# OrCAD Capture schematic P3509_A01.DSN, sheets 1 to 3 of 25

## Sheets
1 0024_MECHANICAL: size Custom
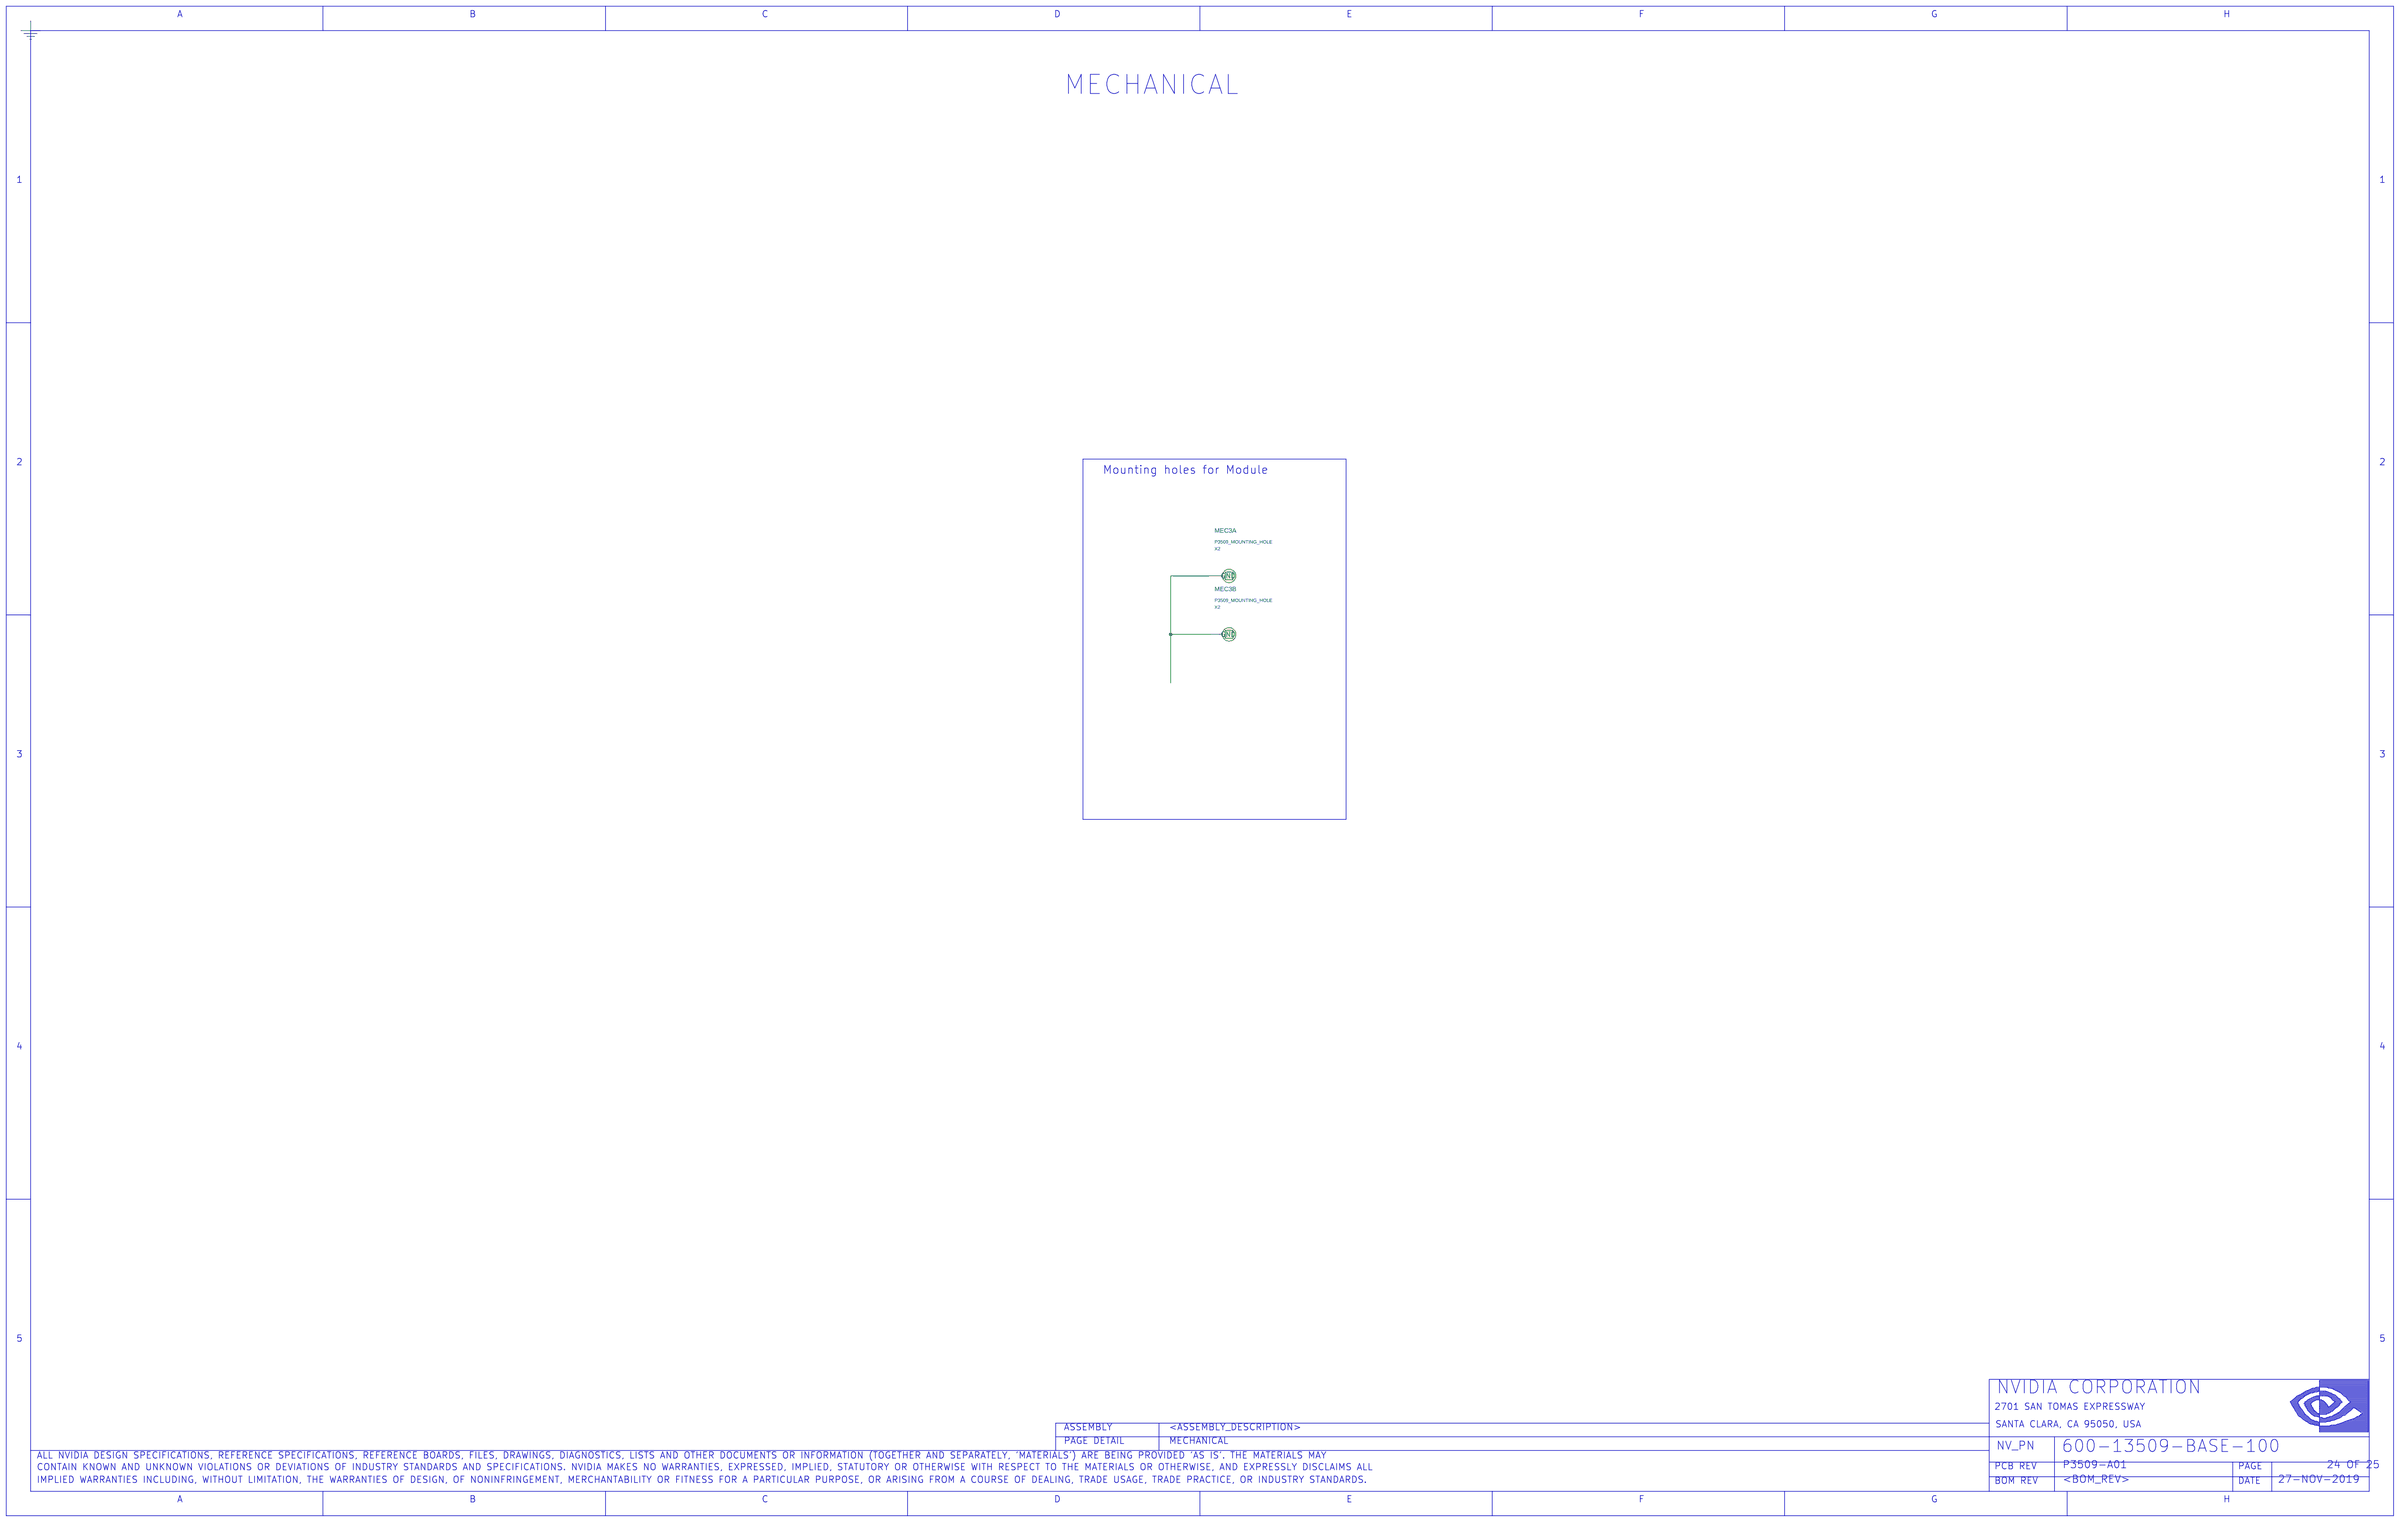
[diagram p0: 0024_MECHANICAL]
2 0023_FAN, DEBUG and EEPROM: size Custom
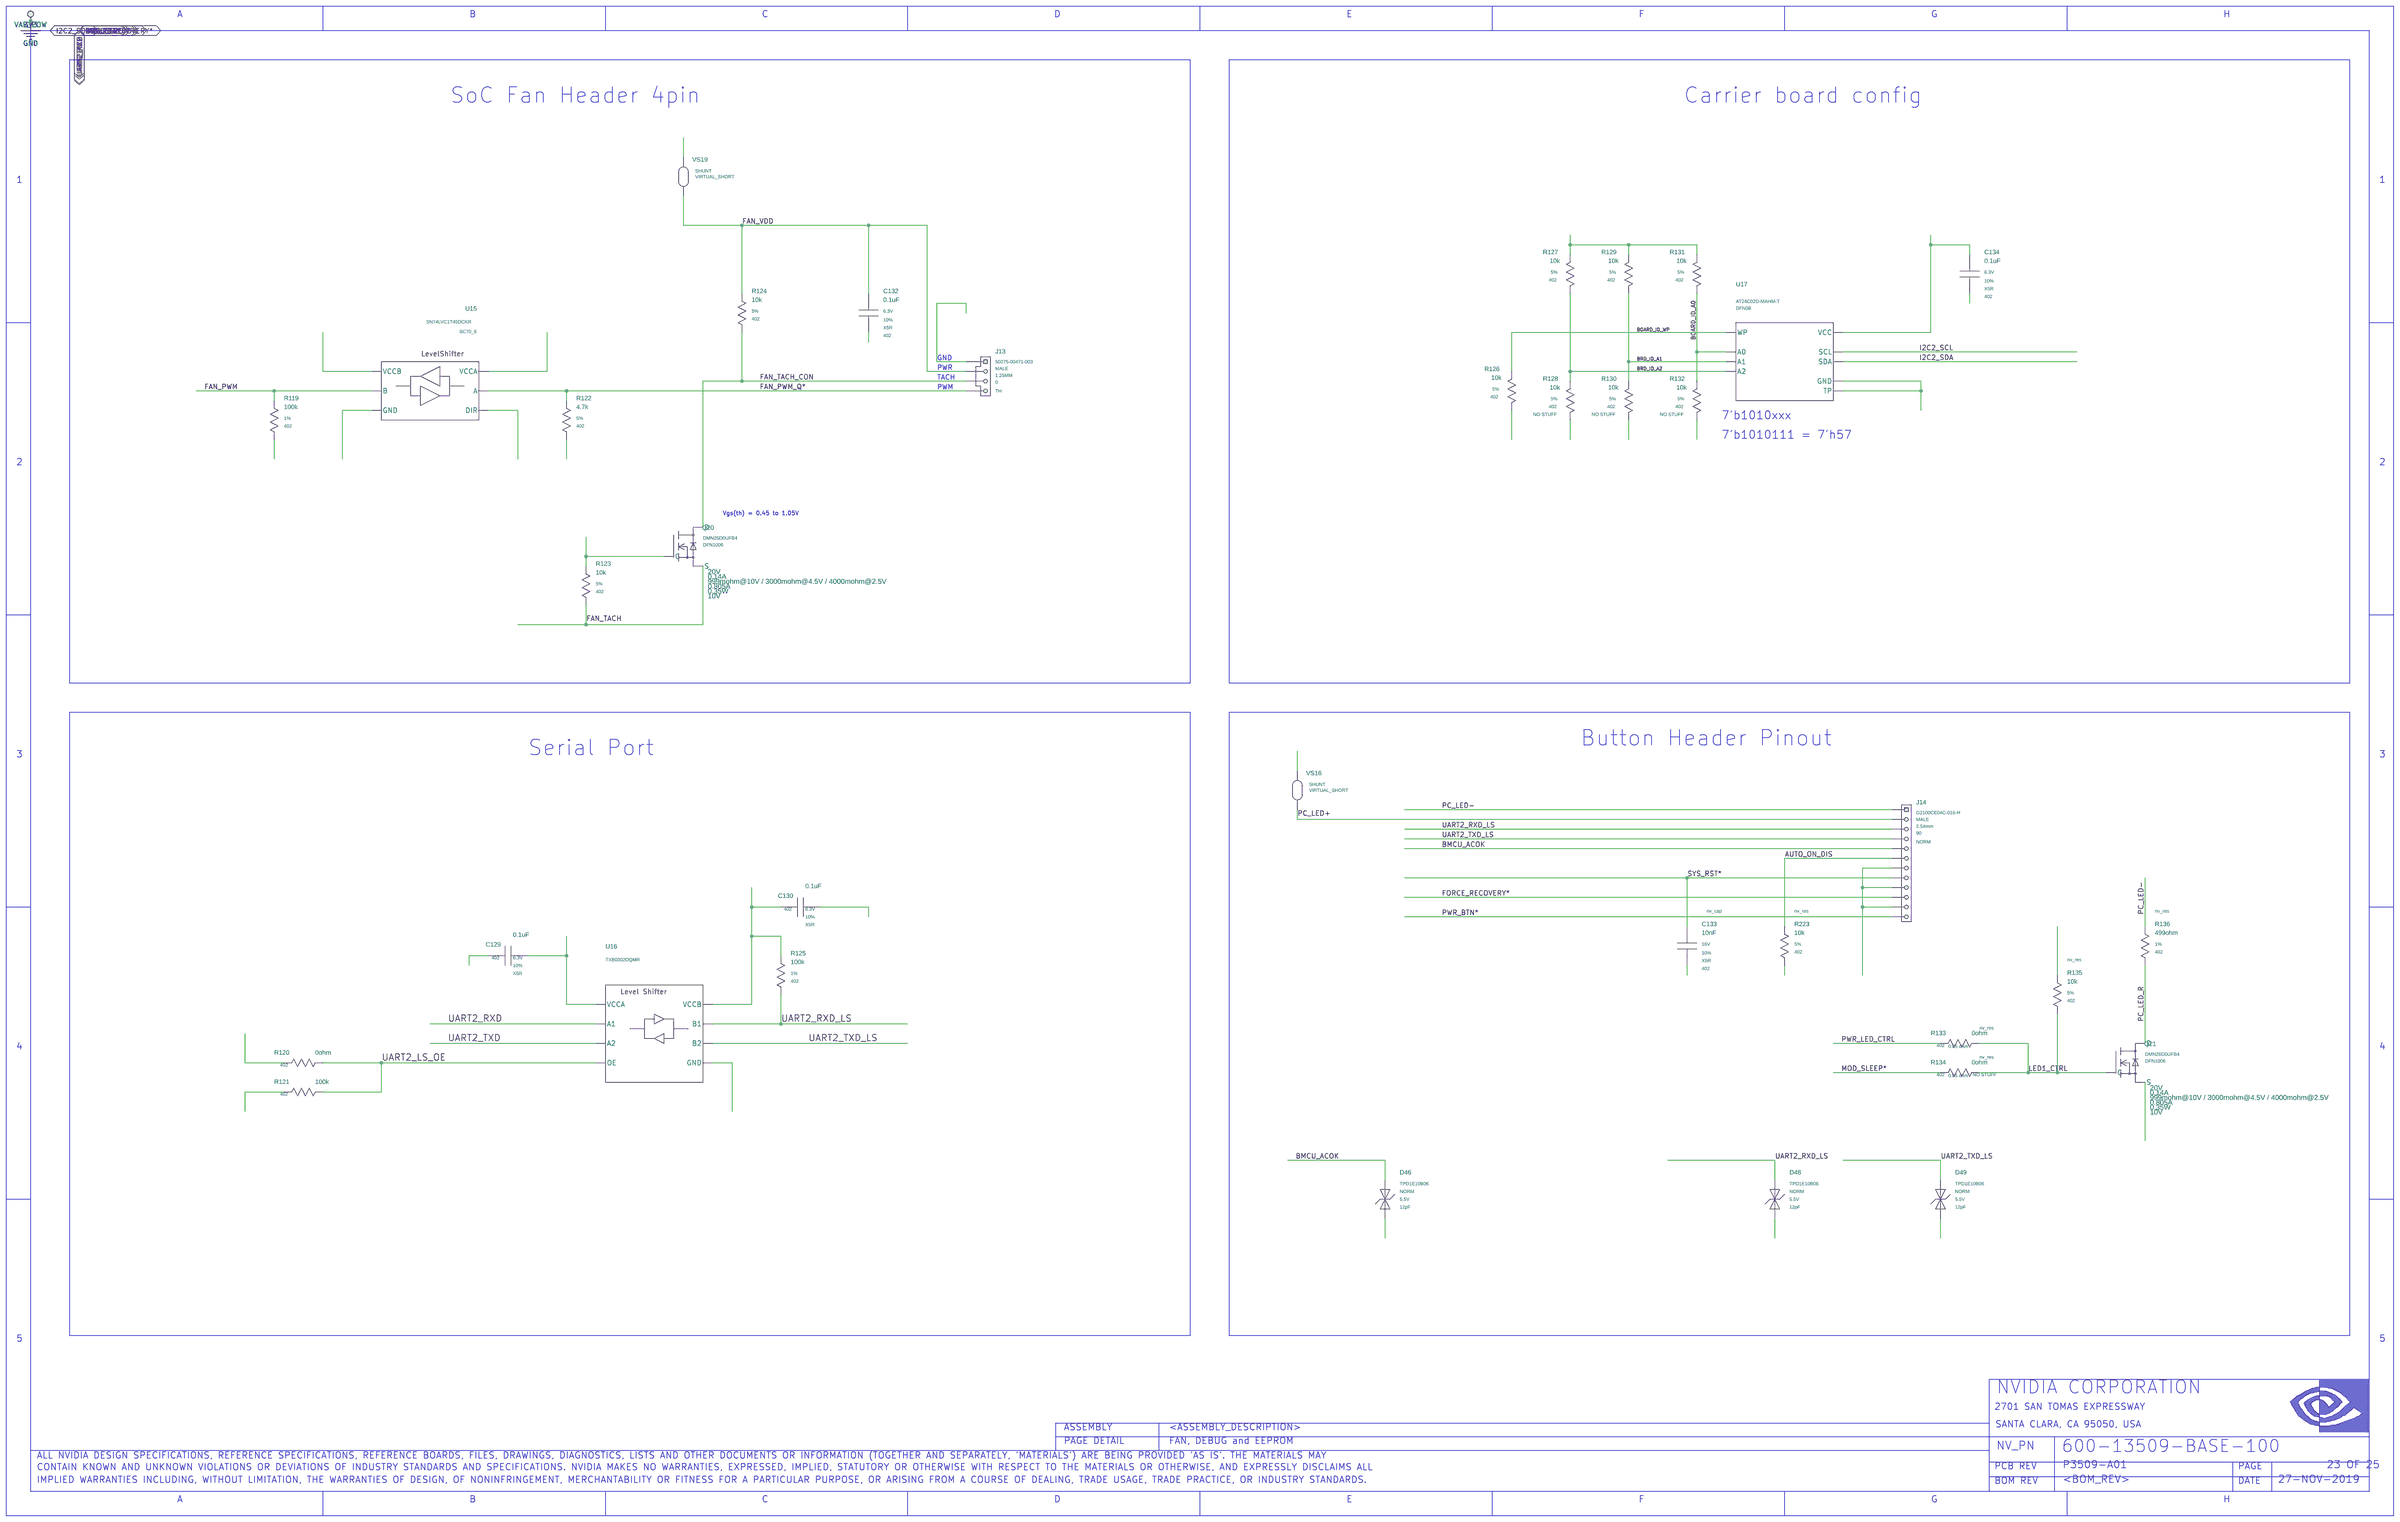
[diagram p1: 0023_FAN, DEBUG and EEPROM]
3 0022_40PIN GPIO Expansion HDR: size Custom
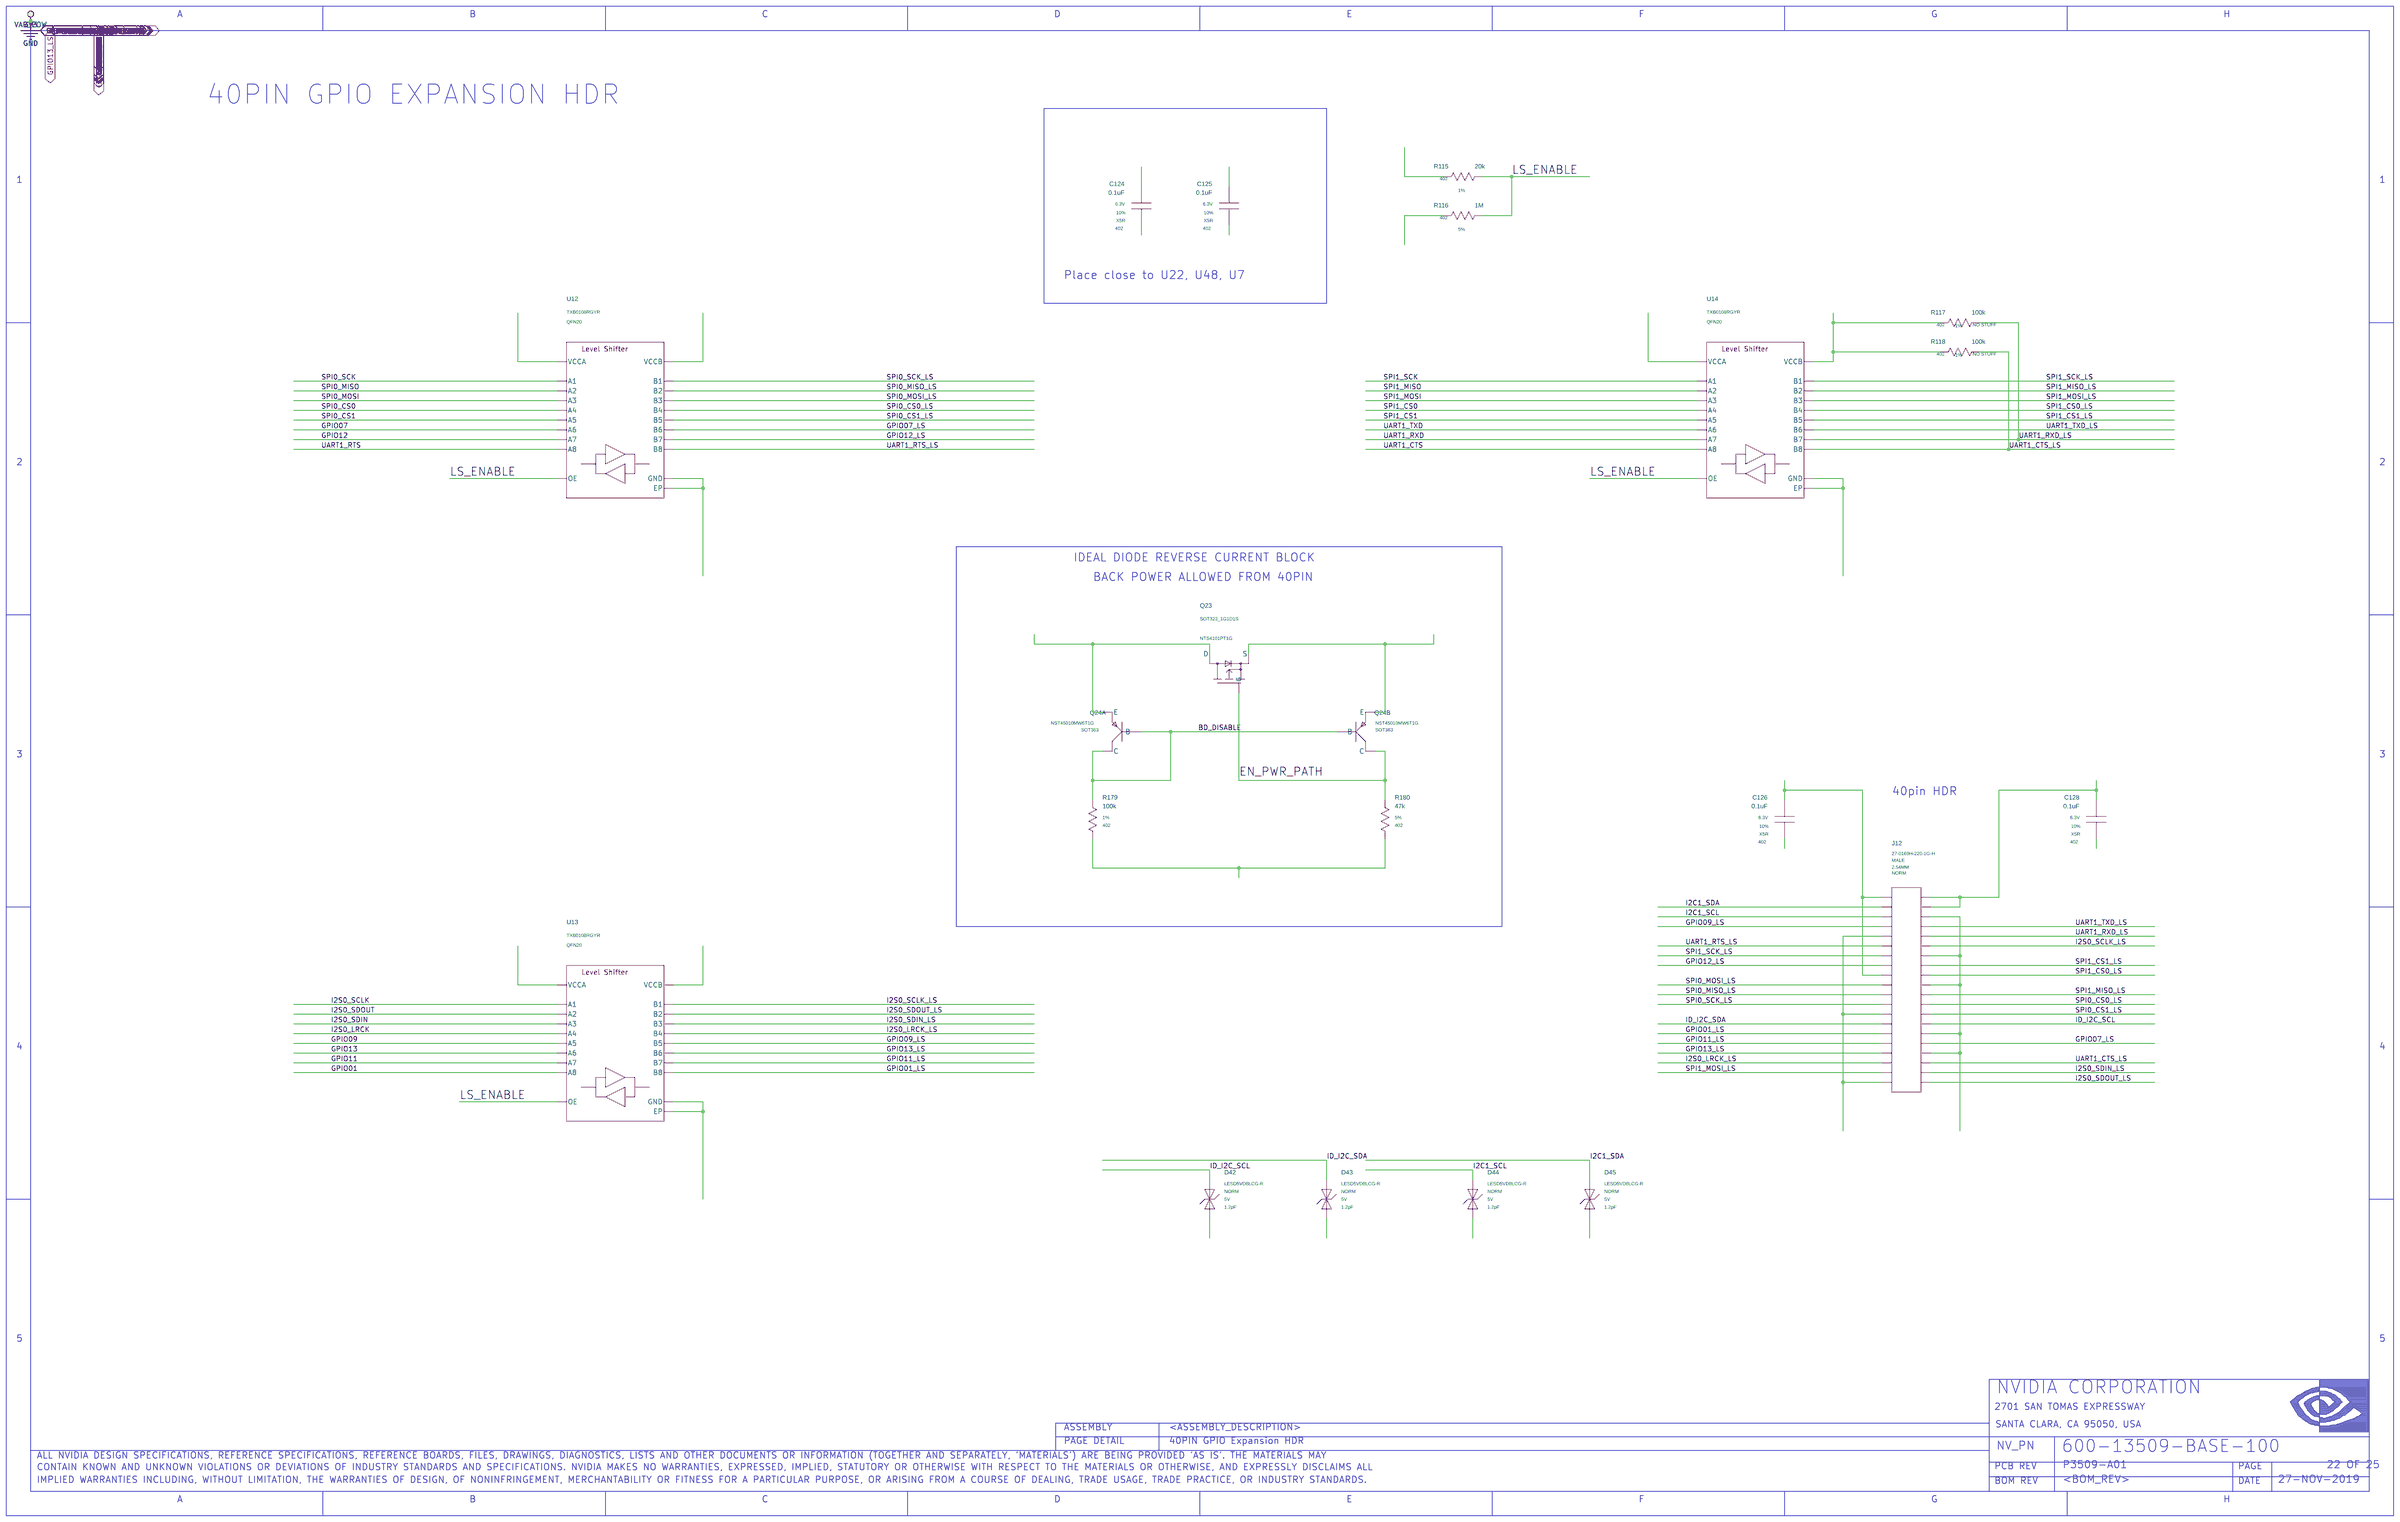
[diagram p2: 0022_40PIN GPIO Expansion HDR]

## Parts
sheet 0022_40PIN GPIO Expansion HDR
C124  0.1uF  [402]
C125  0.1uF  [402]
C126  0.1uF  [402]
C128  0.1uF  [402]
D42  D_ESD  [DIODE_SMD_010X060]
D43  D_ESD  [DIODE_SMD_010X060]
D44  D_ESD  [DIODE_SMD_010X060]
D45  D_ESD  [DIODE_SMD_010X060]
J12  HDR_2X20  [CON_HDR_002X020_TH_ST_M_P025_B]
Q23  Q_FET_P_ENH  [SOT323]
Q24  Q_PNP  [SC70_6]  (sections A,B)
R115  20k  [402]
R116  1M  [402]
R117  100k  [402]
R118  100k  [402]
R179  100k  [402]
R180  47k  [402]
U12  U_LEVSHFT_TXB0108  [QFN020R_P050_0045X0035_T031X021_VIAS]
U13  U_LEVSHFT_TXB0108  [QFN020R_P050_0045X0035_T031X021_VIAS]
U14  U_LEVSHFT_TXB0108  [QFN020R_P050_0045X0035_T031X021_VIAS]
sheet 0023_FAN, DEBUG and EEPROM
C129  0.1uF  [402]
C130  0.1uF  [402]
C132  0.1uF  [402]
C133  10nF  [402]
C134  0.1uF  [402]
D46  D_ESD  [DIODE_SMD_010X060]
D48  D_ESD  [DIODE_SMD_010X060]
D49  D_ESD  [DIODE_SMD_010X060]
J13  CON_B2W_1X4  [CON_MISC_004_TH_ST_M_P013_WTB]
J14  HDR_1X12  [CON_HDR_001X012_TH_RA_M_P025]
Q20  Q_FET_N_ENH  [DFET_003_SMD_010X006_B]
Q21  Q_FET_N_ENH  [DFET_003_SMD_010X006_B]
R119  100k  [402]
R120  0ohm  [402]
R121  100k  [402]
R122  4.7k  [402]
R123  10k  [402]
R124  10k  [402]
R125  100k  [402]
R126  10k  [402]
R127  10k  [402]
R128  10k  [402]
R129  10k  [402]
R130  10k  [402]
R131  10k  [402]
R132  10k  [402]
R133  0ohm  [402]
R134  0ohm  [402]
R135  10k  [402]
R136  499ohm  [402]
R223  10k  [402]
U15  U_LEVSHFT_3STATE  [SC70_6]
U16  U_LEVSHFT_TXB0302  [DFN08_P040_018X012]
U17  U_MEM_EE_I2C  [DFN08_P050_030X020_T016X016]
VS16  VIRTUAL_SHORT  [VIRTUAL_SHORT]
VS19  VIRTUAL_SHORT  [VIRTUAL_SHORT]
sheet 0024_MECHANICAL
MEC3  MOUNTING_HOLE  [MECH_RECT_01000X00790_HOLES_B]  (sections A,B)

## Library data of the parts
C124 = C#1_v2: ASSEMBLY: GPIO_HDR; CDS_LIB: discrete; CDS_PART_NAME: C_0402-0.1UF,X5R,10%,6.3V,039-0007-000; CDS_PHYS_PART_NAME: C_0402-0.1UF,X5R,10%,6.3V,039-0007-000-0.1UF,039-0007-000; CDS_SEC: 1; CHIPS_PART_NAME: C; DEVICE_TYPENAME: C_0402-01UFX5R1063V039-0007-000-01UF039-0007-000; DRAWING: #NAME?; ESL: N/A; ESR: N/A; MAT: X5R; MAX_VOLTAGE: 6.3V; NV_PN: 039-0007-000; PATH: I68; PHYS_PAGE: 22; ROT: 2; SEC: 1; SIGNAL_MODEL: nv_cap; TOL: 10%; VER: 1; XY: (-6300,6600)
C125 = C#1_v2: ASSEMBLY: GPIO_HDR; CDS_LIB: discrete; CDS_PART_NAME: C_0402-0.1UF,X5R,10%,6.3V,039-0007-000; CDS_PHYS_PART_NAME: C_0402-0.1UF,X5R,10%,6.3V,039-0007-000-0.1UF,039-0007-000; CDS_SEC: 1; CHIPS_PART_NAME: C; DEVICE_TYPENAME: C_0402-01UFX5R1063V039-0007-000-01UF039-0007-000; DRAWING: #NAME?; ESL: N/A; ESR: N/A; MAT: X5R; MAX_VOLTAGE: 6.3V; NV_PN: 039-0007-000; PATH: I57; PHYS_PAGE: 22; ROT: 2; SEC: 1; SIGNAL_MODEL: nv_cap; TOL: 10%; VER: 1; XY: (-5850,6600)
C126 = C#1_v2: ASSEMBLY: GPIO_HDR; CDS_LIB: discrete; CDS_PART_NAME: C_0402-0.1UF,X5R,10%,6.3V,039-0007-000; CDS_PHYS_PART_NAME: C_0402-0.1UF,X5R,10%,6.3V,039-0007-000-0.1UF,039-0007-000; CDS_SEC: 1; CHIPS_PART_NAME: C; DEVICE_TYPENAME: C_0402-01UFX5R1063V039-0007-000-01UF039-0007-000; DRAWING: #NAME?; ESL: N/A; ESR: N/A; MAT: X5R; MAX_VOLTAGE: 6.3V; NV_PN: 039-0007-000; PATH: I40; PHYS_PAGE: 22; ROT: 2; SEC: 1; SIGNAL_MODEL: nv_cap; TOL: 10%; VER: 1; XY: (-3000,3450)
C128 = C#1_v2: ASSEMBLY: GPIO_HDR; CDS_LIB: discrete; CDS_PART_NAME: C_0402-0.1UF,X5R,10%,6.3V,039-0007-000; CDS_PHYS_PART_NAME: C_0402-0.1UF,X5R,10%,6.3V,039-0007-000-0.1UF,039-0007-000; CDS_SEC: 1; CHIPS_PART_NAME: C; DEVICE_TYPENAME: C_0402-01UFX5R1063V039-0007-000-01UF039-0007-000; DRAWING: #NAME?; ESL: N/A; ESR: N/A; MAT: X5R; MAX_VOLTAGE: 6.3V; NV_PN: 039-0007-000; PATH: I31; PHYS_PAGE: 22; ROT: 2; SEC: 1; SIGNAL_MODEL: nv_cap; TOL: 10%; VER: 1; XY: (-1400,3450)
D42 = D_ESD: ASSEMBLY: GPIO_HDR; BREAKDOWN_VOLTAGE_MIN_TYP: 5.5V; CAPACITANCE_MAX_TYP: 1.2pF; CDS_LIB: discrete; CDS_PART_NAME: D_ESD_NORM-LESD5VD8LCG-R,1 LINE,BI-DIRECTIONAL,5V,0.05UA,5.5V,10V@2A,1.2PF,090-0172-000; CDS_PHYS_PART_NAME: D_ESD_NORM-LESD5VD8LCG-R,1 LINE,BI-DIRECTIONAL,5V,0.05UA,5.5V,10V@2A,1.2PF,090-0172-000-090-0172-000; CDS_SEC: 1; CLAMPING_VOLTAGE: 10V@2A; CONFIGURATION: 1 Line; DEVICE_TYPENAME: D_ESD_NORM-LESD5VD8LCG-R1LINEBI-DIRECTIONAL5V005UA55V10V2A12PF090-0172-000-090-0172-000; DRAWING: #NAME?; MAX_REVERSE_LEAKAGE_CURRENT: 0.05uA; MAX_REVERSE_VOLTAGE: 5V; NV_NAME: LESD5VD8LCG-R; NV_PN: 090-0172-000; PACK_TYPE: NORM; PATH: I84; PHYS_PAGE: 22; POLARITY: Bi-Directional; ROT: 0; SEC: 1; VER: 2; XY: (-5950,1500)
D43 = D_ESD: ASSEMBLY: GPIO_HDR; BREAKDOWN_VOLTAGE_MIN_TYP: 5.5V; CAPACITANCE_MAX_TYP: 1.2pF; CDS_LIB: discrete; CDS_PART_NAME: D_ESD_NORM-LESD5VD8LCG-R,1 LINE,BI-DIRECTIONAL,5V,0.05UA,5.5V,10V@2A,1.2PF,090-0172-000; CDS_PHYS_PART_NAME: D_ESD_NORM-LESD5VD8LCG-R,1 LINE,BI-DIRECTIONAL,5V,0.05UA,5.5V,10V@2A,1.2PF,090-0172-000-090-0172-000; CDS_SEC: 1; CLAMPING_VOLTAGE: 10V@2A; CONFIGURATION: 1 Line; DEVICE_TYPENAME: D_ESD_NORM-LESD5VD8LCG-R1LINEBI-DIRECTIONAL5V005UA55V10V2A12PF090-0172-000-090-0172-000; DRAWING: #NAME?; MAX_REVERSE_LEAKAGE_CURRENT: 0.05uA; MAX_REVERSE_VOLTAGE: 5V; NV_NAME: LESD5VD8LCG-R; NV_PN: 090-0172-000; PACK_TYPE: NORM; PATH: I82; PHYS_PAGE: 22; POLARITY: Bi-Directional; ROT: 0; SEC: 1; VER: 2; XY: (-5350,1500)
D44 = D_ESD: ASSEMBLY: GPIO_HDR; BREAKDOWN_VOLTAGE_MIN_TYP: 5.5V; CAPACITANCE_MAX_TYP: 1.2pF; CDS_LIB: discrete; CDS_PART_NAME: D_ESD_NORM-LESD5VD8LCG-R,1 LINE,BI-DIRECTIONAL,5V,0.05UA,5.5V,10V@2A,1.2PF,090-0172-000; CDS_PHYS_PART_NAME: D_ESD_NORM-LESD5VD8LCG-R,1 LINE,BI-DIRECTIONAL,5V,0.05UA,5.5V,10V@2A,1.2PF,090-0172-000-090-0172-000; CDS_SEC: 1; CLAMPING_VOLTAGE: 10V@2A; CONFIGURATION: 1 Line; DEVICE_TYPENAME: D_ESD_NORM-LESD5VD8LCG-R1LINEBI-DIRECTIONAL5V005UA55V10V2A12PF090-0172-000-090-0172-000; DRAWING: #NAME?; MAX_REVERSE_LEAKAGE_CURRENT: 0.05uA; MAX_REVERSE_VOLTAGE: 5V; NV_NAME: LESD5VD8LCG-R; NV_PN: 090-0172-000; PACK_TYPE: NORM; PATH: I79; PHYS_PAGE: 22; POLARITY: Bi-Directional; ROT: 0; SEC: 1; VER: 2; XY: (-4600,1500)
D45 = D_ESD: ASSEMBLY: GPIO_HDR; BREAKDOWN_VOLTAGE_MIN_TYP: 5.5V; CAPACITANCE_MAX_TYP: 1.2pF; CDS_LIB: discrete; CDS_PART_NAME: D_ESD_NORM-LESD5VD8LCG-R,1 LINE,BI-DIRECTIONAL,5V,0.05UA,5.5V,10V@2A,1.2PF,090-0172-000; CDS_PHYS_PART_NAME: D_ESD_NORM-LESD5VD8LCG-R,1 LINE,BI-DIRECTIONAL,5V,0.05UA,5.5V,10V@2A,1.2PF,090-0172-000-090-0172-000; CDS_SEC: 1; CLAMPING_VOLTAGE: 10V@2A; CONFIGURATION: 1 Line; DEVICE_TYPENAME: D_ESD_NORM-LESD5VD8LCG-R1LINEBI-DIRECTIONAL5V005UA55V10V2A12PF090-0172-000-090-0172-000; DRAWING: #NAME?; MAX_REVERSE_LEAKAGE_CURRENT: 0.05uA; MAX_REVERSE_VOLTAGE: 5V; NV_NAME: LESD5VD8LCG-R; NV_PN: 090-0172-000; PACK_TYPE: NORM; PATH: I78; PHYS_PAGE: 22; POLARITY: Bi-Directional; ROT: 0; SEC: 1; VER: 2; XY: (-4000,1500)
J12 = HDR_2X20: ANGLE: 0; ASSEMBLY: GPIO_HDR; CDS_LIB: electro_mechanic; CDS_PART_NAME: HDR_2X20_NORM-27-0169H-220-1G-H,MALE,2.54MM,0,YES,NO,NO,1000 V,3 A,074-0221-000; CDS_PHYS_PART_NAME: HDR_2X20_NORM-27-0169H-220-1G-H,MALE,2.54MM,0,YES,NO,NO,1000 V,3 A,074-0221-000-074-0221-000; CDS_SEC: 1; DEVICE_TYPENAME: HDR_2X20_NORM-27-0169H-220-1G-HMALE254MM0YESNONO1000V3A074-0221-000-074-0221-000; DRAWING: #NAME?; GENDER: MALE; LATCHING: NO; MAX_CURRENT: 3:00 AM; MAX_VOLTAGE: 1000 V; NV_NAME: 27-0169H-220-1G-H; NV_PN: 074-0221-000; PACK_TYPE: NORM; PATH: I1; PHYS_PAGE: 22; PITCH: 2.54MM; REFLOW: YES; ROT: 0; SEC: 1; SHROUDED: NO; VER: 1; XY: (-2350,2550)
Q23 = Q_FET_P_ENH#2: ASSEMBLY: GPIO_HDR; CDS_LIB: discrete; CDS_PART_NAME: Q_FET_P_ENH_SOT323_1G1D1S-NTS4101PT1G,-20V,0MOHM@10V / 120MOHM@4.5V / 160MOHM@2.5V,-1.37A,-4A,8V,0.329W,[ ]@10V / 9NC@4.5V / [A; CDS_PHYS_PART_NAME: Q_FET_P_ENH_SOT323_1G1D1S-NTS4101PT1G,-20V,0MOHM@10V / 120MOHM@4.5V / 160MOHM@2.5V,-1.37A,-4A,8V,0.329W,[ ]@10V / 9NC@4.5V / [B; CDS_SEC: 1; CONTINUOUS_CURRENT: -1.37A; DEVICE_TYPENAME: Q_FET_P_ENH_SOT323_1G1D1S-NTS4101PT1G-20V0MOHM10V120MOHM45V160MOHM25V-137A-4A8V0329W10V9NC45VB; DRAWING: #NAME?; MAX_CURRENT: -4A; MAX_VOLTAGE: -20V; MAX_WATTAGE: 0.329W; NV_NAME: NTS4101PT1G; NV_PN: 300-0859-000; PACK_TYPE: SOT323_1G1D1S; PATH: I203; PHYS_PAGE: 22; Q_G: [ ]@10V / 9nC@4.5V / [ ]@2.5V; ROT: 4; R_DS_ON: 0mohm@10V / 120mohm@4.5V / 160mohm@2.5V; SEC: 1; SEC_TYPE: SOT323_1G1D1S; VER: 10; V_BE_GS: 8V; XY: (-5850,4200)
Q24 = Q_PNP: ASSEMBLY: GPIO_HDR; CDS_LIB: discrete; CDS_PART_NAME: Q_PNP_SOT363-NST45010MW6T1G,-45V,-50V,-0.1A,-0.1A,-5V,0.1MW,300-0906-000; CDS_PHYS_PART_NAME: Q_PNP_SOT363-NST45010MW6T1G,-45V,-50V,-0.1A,-0.1A,-5V,0.1MW,300-0906-000-300-0906-000; CDS_SEC: 1; CONTINUOUS_CURRENT: -0.1A; DEVICE_TYPENAME: Q_PNP_SOT363-NST45010MW6T1G-45V-50V-01A-01A-5V01MW300-0906-000-300-0906-000; DRAWING: #NAME?; MAX_CURRENT: -0.1A; MAX_VOLTAGE: -45V; MAX_WATTAGE: 0.1mW; NV_NAME: NST45010MW6T1G; NV_PN: 300-0906-000; PACK_TYPE: SOT363; PATH: I210; PHYS_PAGE: 22; ROT: 2; SEC: 1; VER: 2; V_BE_GS: -5V; V_CE_SAT: -50V; XY: (-6400,3900)
R115 = R#1: ASSEMBLY: GPIO_HDR; CDS_LIB: discrete; CDS_PART_NAME: R_0402-20K,1 %,62.5MW,195-0150-000; CDS_PHYS_PART_NAME: R_0402-20K,1 %,62.5MW,195-0150-000-195-0150-000,20K; CDS_SEC: 1; CHIPS_PART_NAME: R; DEVICE_TYPENAME: R_0402-20K1625MW195-0150-000-195-0150-00020K; DRAWING: #NAME?; MAX_WATTAGE: 62.5mW; NV_PN: 195-0150-000; PATH: I98; PHYS_PAGE: 22; ROT: 0; SEC: 1; SIGNAL_MODEL: nv_res; TOL: 1%; VER: 1; XY: (-4650,6750)
R116 = R#1: ASSEMBLY: GPIO_HDR; CDS_LIB: discrete; CDS_PART_NAME: R_0402-1M,5 %,62.5MW,195-0488-000; CDS_PHYS_PART_NAME: R_0402-1M,5 %,62.5MW,195-0488-000-195-0488-000,1M; CDS_SEC: 1; CHIPS_PART_NAME: R; DEVICE_TYPENAME: R_0402-1M5625MW195-0488-000-195-0488-0001M; DRAWING: #NAME?; MAX_WATTAGE: 62.5mW; NV_PN: 195-0488-000; PATH: I100; PHYS_PAGE: 22; ROT: 0; SEC: 1; SIGNAL_MODEL: nv_res; TOL: 5%; VER: 1; XY: (-4650,6550)
R117 = R#1: ASSEMBLY: GPIO_HDR; CDS_LIB: discrete; CDS_PART_NAME: R_0402-100K,1 %,62.5MW,195-0005-000; CDS_PHYS_PART_NAME: R_0402-100K,1 %,62.5MW,195-0005-000-100K,195-0005-000; CDS_SEC: 1; CHIPS_PART_NAME: R; DEVICE_TYPENAME: R_0402-100K1625MW195-0005-000-100K195-0005-000; DRAWING: #NAME?; MAX_WATTAGE: 62.5mW; NV_PN: 195-0005-000; PATH: I13; PHYS_PAGE: 22; ROT: 0; SEC: 1; SIGNAL_MODEL: nv_res; SKU: NO STUFF; TOL: 1%; VER: 1; XY: (-2100,6000)
R118 = R#1: ASSEMBLY: GPIO_HDR; CDS_LIB: discrete; CDS_PART_NAME: R_0402-100K,1 %,62.5MW,195-0005-000; CDS_PHYS_PART_NAME: R_0402-100K,1 %,62.5MW,195-0005-000-100K,195-0005-000; CDS_SEC: 1; CHIPS_PART_NAME: R; DEVICE_TYPENAME: R_0402-100K1625MW195-0005-000-100K195-0005-000; DRAWING: #NAME?; MAX_WATTAGE: 62.5mW; NV_PN: 195-0005-000; PATH: I14; PHYS_PAGE: 22; ROT: 0; SEC: 1; SIGNAL_MODEL: nv_res; SKU: NO STUFF; TOL: 1%; VER: 1; XY: (-2100,5850)
R179 = R: ASSEMBLY: GPIO_HDR; CDS_LIB: discrete; CDS_PART_NAME: R_0402-100K,1 %,62.5MW,195-0005-000; CDS_PHYS_PART_NAME: R_0402-100K,1 %,62.5MW,195-0005-000-100K,195-0005-000; CDS_SEC: 1; DEVICE_TYPENAME: R_0402-100K1625MW195-0005-000-100K195-0005-000; DRAWING: #NAME?; MAX_WATTAGE: 62.5mW; NV_PN: 195-0005-000; PATH: I211; PHYS_PAGE: 22; ROT: 0; SEC: 1; TOL: 1%; VER: 2; XY: (-6550,3450)
R180 = R: ASSEMBLY: GPIO_HDR; CDS_LIB: discrete; CDS_PART_NAME: R_0402-47K,5 %,62.5MW,195-0599-000; CDS_PHYS_PART_NAME: R_0402-47K,5 %,62.5MW,195-0599-000-195-0599-000,47K; CDS_SEC: 1; DEVICE_TYPENAME: R_0402-47K5625MW195-0599-000-195-0599-00047K; DRAWING: #NAME?; MAX_WATTAGE: 62.5mW; NV_PN: 195-0599-000; PATH: I212; PHYS_PAGE: 22; ROT: 0; SEC: 1; TOL: 5%; VER: 2; XY: (-5050,3450)
U12 = U_LEVSHFT_TXB0108: ASSEMBLY: GPIO_HDR; CDS_LIB: digital; CDS_PART_NAME: U_LEVSHFT_TXB0108_QFN20-TXB0108RGYR,LEVEL SHIFTER,115-1921-000; CDS_PHYS_PART_NAME: U_LEVSHFT_TXB0108_QFN20-TXB0108RGYR,LEVEL SHIFTER,115-1921-000-115-1921-000; CDS_SEC: 1; DEVICE_TYPENAME: U_LEVSHFT_TXB0108_QFN20-TXB0108RGYRLEVELSHIFTER115-1921-000-115-1921-000; DRAWING: #NAME?; FUNCTION: Level Shifter; NV_NAME: TXB0108RGYR; NV_PN: 115-1921-000; PACK_TYPE: QFN20; PATH: I97; PHYS_PAGE: 22; ROT: 0; SEC: 1; VER: 1; XY: (-9000,5550)
U13 = U_LEVSHFT_TXB0108: ASSEMBLY: GPIO_HDR; CDS_LIB: digital; CDS_PART_NAME: U_LEVSHFT_TXB0108_QFN20-TXB0108RGYR,LEVEL SHIFTER,115-1921-000; CDS_PHYS_PART_NAME: U_LEVSHFT_TXB0108_QFN20-TXB0108RGYR,LEVEL SHIFTER,115-1921-000-115-1921-000; CDS_SEC: 1; DEVICE_TYPENAME: U_LEVSHFT_TXB0108_QFN20-TXB0108RGYRLEVELSHIFTER115-1921-000-115-1921-000; DRAWING: #NAME?; FUNCTION: Level Shifter; NV_NAME: TXB0108RGYR; NV_PN: 115-1921-000; PACK_TYPE: QFN20; PATH: I115; PHYS_PAGE: 22; ROT: 0; SEC: 1; VER: 1; XY: (-9000,2350)
U14 = U_LEVSHFT_TXB0108: ASSEMBLY: GPIO_HDR; CDS_LIB: digital; CDS_PART_NAME: U_LEVSHFT_TXB0108_QFN20-TXB0108RGYR,LEVEL SHIFTER,115-1921-000; CDS_PHYS_PART_NAME: U_LEVSHFT_TXB0108_QFN20-TXB0108RGYR,LEVEL SHIFTER,115-1921-000-115-1921-000; CDS_SEC: 1; DEVICE_TYPENAME: U_LEVSHFT_TXB0108_QFN20-TXB0108RGYRLEVELSHIFTER115-1921-000-115-1921-000; DRAWING: #NAME?; FUNCTION: Level Shifter; NV_NAME: TXB0108RGYR; NV_PN: 115-1921-000; PACK_TYPE: QFN20; PATH: I19; PHYS_PAGE: 22; ROT: 0; SEC: 1; VER: 1; XY: (-3150,5550)
C129 = C: ASSEMBLY: DEBUG; CDS_LIB: discrete; CDS_PART_NAME: C_0402-0.1UF,X5R,10%,6.3V,039-0007-000; CDS_PHYS_PART_NAME: C_0402-0.1UF,X5R,10%,6.3V,039-0007-000-0.1UF,039-0007-000; CDS_SEC: 1; DEVICE_TYPENAME: C_0402-01UFX5R1063V039-0007-000-01UF039-0007-000; DRAWING: #NAME?; MAT: X5R; MAX_VOLTAGE: 6.3V; NV_PN: 039-0007-000; PATH: I77; PHYS_PAGE: 23; ROT: 0; SEC: 1; SIGNAL_MODEL: nv_cap; TOL: 10%; VER: 2; XY: (-9550,2750)
C130 = C: ASSEMBLY: DEBUG; CDS_LIB: discrete; CDS_PART_NAME: C_0402-0.1UF,X5R,10%,6.3V,039-0007-000; CDS_PHYS_PART_NAME: C_0402-0.1UF,X5R,10%,6.3V,039-0007-000-0.1UF,039-0007-000; CDS_SEC: 1; DEVICE_TYPENAME: C_0402-01UFX5R1063V039-0007-000-01UF039-0007-000; DRAWING: #NAME?; MAT: X5R; MAX_VOLTAGE: 6.3V; NV_PN: 039-0007-000; PATH: I57; PHYS_PAGE: 23; ROT: 0; SEC: 1; SIGNAL_MODEL: nv_cap; TOL: 10%; VER: 2; XY: (-8050,3000)
C132 = C#1_v2: ASSEMBLY: FAN; CDS_LIB: discrete; CDS_PART_NAME: C_0402-0.1UF,X5R,10%,6.3V,039-0007-000; CDS_PHYS_PART_NAME: C_0402-0.1UF,X5R,10%,6.3V,039-0007-000-0.1UF,039-0007-000; CDS_SEC: 1; CHIPS_PART_NAME: C; DEVICE_TYPENAME: C_0402-01UFX5R1063V039-0007-000-01UF039-0007-000; DRAWING: #NAME?; MAT: X5R; MAX_VOLTAGE: 6.3V; NV_PN: 039-0007-000; PATH: I2; PHYS_PAGE: 23; ROT: 0; SEC: 1; SIGNAL_MODEL: nv_cap; TOL: 10%; VER: 1; XY: (-7700,6050)
C133 = C#1_v2: ASSEMBLY: AUTOMATION; CDS_LIB: discrete; CDS_PART_NAME: C_0402-10NF,X5R,10%,16V,039-0024-000; CDS_PHYS_PART_NAME: C_0402-10NF,X5R,10%,16V,039-0024-000-039-0024-000,10NF; CDS_SEC: 1; CHIPS_PART_NAME: C; DEVICE_TYPENAME: C_0402-10NFX5R1016V039-0024-000-039-0024-00010NF; DRAWING: #NAME?; MAT: X5R; MAX_VOLTAGE: 16V; NV_PN: 039-0024-000; PATH: I31; PHYS_PAGE: 23; ROT: 0; SEC: 1; SIGNAL_MODEL: nv_cap; TOL: 10%; VER: 1; XY: (-3500,2800)
C134 = C#1_v2: ASSEMBLY: L4T_EEPROM; CDS_LIB: discrete; CDS_PART_NAME: C_0402-0.1UF,X5R,10%,6.3V,039-0007-000; CDS_PHYS_PART_NAME: C_0402-0.1UF,X5R,10%,6.3V,039-0007-000-0.1UF,039-0007-000; CDS_SEC: 1; CHIPS_PART_NAME: C; DEVICE_TYPENAME: C_0402-01UFX5R1063V039-0007-000-01UF039-0007-000; DRAWING: #NAME?; MAT: X5R; MAX_VOLTAGE: 6.3V; NV_PN: 039-0007-000; PATH: I11; PHYS_PAGE: 23; ROT: 0; SEC: 1; SIGNAL_MODEL: nv_cap; TOL: 10%; VER: 1; XY: (-2050,6250)
D46 = D_ESD: ASSEMBLY: AUTOMATION; BREAKDOWN_VOLTAGE_MIN_TYP: 6V; CAPACITANCE_MAX_TYP: 12pF; CDS_LIB: discrete; CDS_PART_NAME: D_ESD_NORM-TPD1E10B06,1 LINE,BI-DIRECTIONAL,5.5V,0.1UA,6V,10V@1A,12PF,090-0243-000; CDS_PHYS_PART_NAME: D_ESD_NORM-TPD1E10B06,1 LINE,BI-DIRECTIONAL,5.5V,0.1UA,6V,10V@1A,12PF,090-0243-000-090-0243-000; CDS_SEC: 1; CLAMPING_VOLTAGE: 10V@1A; CONFIGURATION: 1 Line; DEVICE_TYPENAME: D_ESD_NORM-TPD1E10B061LINEBI-DIRECTIONAL55V01UA6V10V1A12PF090-0243-000-090-0243-000; DRAWING: #NAME?; MAX_REVERSE_LEAKAGE_CURRENT: 0.1uA; MAX_REVERSE_VOLTAGE: 5.5V; NV_NAME: TPD1E10B06; NV_PN: 090-0243-000; PACK_TYPE: NORM; PATH: I54; PHYS_PAGE: 23; POLARITY: Bi-Directional; ROT: 0; SEC: 1; VER: 2; XY: (-5050,1500)
D48 = D_ESD: ASSEMBLY: AUTOMATION; BREAKDOWN_VOLTAGE_MIN_TYP: 6V; CAPACITANCE_MAX_TYP: 12pF; CDS_LIB: discrete; CDS_PART_NAME: D_ESD_NORM-TPD1E10B06,1 LINE,BI-DIRECTIONAL,5.5V,0.1UA,6V,10V@1A,12PF,090-0243-000; CDS_PHYS_PART_NAME: D_ESD_NORM-TPD1E10B06,1 LINE,BI-DIRECTIONAL,5.5V,0.1UA,6V,10V@1A,12PF,090-0243-000-090-0243-000; CDS_SEC: 1; CLAMPING_VOLTAGE: 10V@1A; CONFIGURATION: 1 Line; DEVICE_TYPENAME: D_ESD_NORM-TPD1E10B061LINEBI-DIRECTIONAL55V01UA6V10V1A12PF090-0243-000-090-0243-000; DRAWING: #NAME?; MAX_REVERSE_LEAKAGE_CURRENT: 0.1uA; MAX_REVERSE_VOLTAGE: 5.5V; NV_NAME: TPD1E10B06; NV_PN: 090-0243-000; PACK_TYPE: NORM; PATH: I35; PHYS_PAGE: 23; POLARITY: Bi-Directional; ROT: 0; SEC: 1; VER: 2; XY: (-3050,1500)
D49 = D_ESD: ASSEMBLY: AUTOMATION; BREAKDOWN_VOLTAGE_MIN_TYP: 6V; CAPACITANCE_MAX_TYP: 12pF; CDS_LIB: discrete; CDS_PART_NAME: D_ESD_NORM-TPD1E10B06,1 LINE,BI-DIRECTIONAL,5.5V,0.1UA,6V,10V@1A,12PF,090-0243-000; CDS_PHYS_PART_NAME: D_ESD_NORM-TPD1E10B06,1 LINE,BI-DIRECTIONAL,5.5V,0.1UA,6V,10V@1A,12PF,090-0243-000-090-0243-000; CDS_SEC: 1; CLAMPING_VOLTAGE: 10V@1A; CONFIGURATION: 1 Line; DEVICE_TYPENAME: D_ESD_NORM-TPD1E10B061LINEBI-DIRECTIONAL55V01UA6V10V1A12PF090-0243-000-090-0243-000; DRAWING: #NAME?; MAX_REVERSE_LEAKAGE_CURRENT: 0.1uA; MAX_REVERSE_VOLTAGE: 5.5V; NV_NAME: TPD1E10B06; NV_PN: 090-0243-000; PACK_TYPE: NORM; PATH: I33; PHYS_PAGE: 23; POLARITY: Bi-Directional; ROT: 0; SEC: 1; VER: 2; XY: (-2200,1500)
J13 = CON_B2W_1X4: ANGLE: 0; ASSEMBLY: FAN; CDS_LIB: electro_mechanic; CDS_PART_NAME: CON_B2W_1X4_TH-50275-00471-003,MALE,1.25MM,0,YES,YES,NO,NO,N/A,NA,NA,064-0267-000; CDS_PHYS_PART_NAME: CON_B2W_1X4_TH-50275-00471-003,MALE,1.25MM,0,YES,YES,NO,NO,N/A,NA,NA,064-0267-000-064-0267-000; CDS_SEC: 1; DEVICE_TYPENAME: CON_B2W_1X4_TH-50275-00471-003MALE125MM0YESYESNONONANANA064-0267-000-064-0267-000; DRAWING: #NAME?; EMI_GROUND_TAB: NO; GENDER: MALE; LATCHING: NO; MAX_CURRENT: NA; MAX_VOLTAGE: NA; NV_NAME: 50275-00471-003; NV_PN: 064-0267-000; PACK_TYPE: TH; PATH: I91; PHYS_PAGE: 23; PITCH: 1.25MM; REFLOW: YES; ROT: 0; SEC: 1; SEC_TYPE: TH; SHIELDED: N/A; SHROUDED: YES; VER: 1; XY: (-7100,5800)
J14 = HDR_1X12: ANGLE: 90; ASSEMBLY: AUTOMATION; CDS_LIB: electro_mechanic; CDS_PART_NAME: HDR_1X12_NORM-G2100CE04C-016-H,MALE,2.54MM,90,YES,NO,NO,125 V,3 A,074-0239-000; CDS_PHYS_PART_NAME: HDR_1X12_NORM-G2100CE04C-016-H,MALE,2.54MM,90,YES,NO,NO,125 V,3 A,074-0239-000-074-0239-000; CDS_SEC: 1; DEVICE_TYPENAME: HDR_1X12_NORM-G2100CE04C-016-HMALE254MM90YESNONO125V3A074-0239-000-074-0239-000; DRAWING: #NAME?; GENDER: MALE; LATCHING: NO; MAX_CURRENT: 3:00 AM; MAX_VOLTAGE: 125 V; NV_NAME: G2100CE04C-016-H; NV_PN: 074-0239-000; PACK_TYPE: NORM; PATH: I25; PHYS_PAGE: 23; PITCH: 2.54mm; REFLOW: YES; ROT: 0; SEC: 1; SHROUDED: NO; VER: 1; XY: (-2400,3250)
Q20 = Q_FET_N_ENH#1: ASSEMBLY: FAN; CDS_LIB: discrete; CDS_PART_NAME: Q_FET_N_ENH_DFN1006-DMN26D0UFB4,20V,999MOHM@10V / 3000MOHM@4.5V / 4000MOHM@2.5V,0.14A,0.805A,10V,0.35W,999NC@10V / 0NC@4.5V / A; CDS_PHYS_PART_NAME: Q_FET_N_ENH_DFN1006-DMN26D0UFB4,20V,999MOHM@10V / 3000MOHM@4.5V / 4000MOHM@2.5V,0.14A,0.805A,10V,0.35W,999NC@10V / 0NC@4.5V / B; CDS_SEC: 1; CONTINUOUS_CURRENT: 0.14A; CaptureCellPackProp: Q_FET_N_ENH##1; DEVICE_TYPENAME: Q_FET_N_ENH_DFN1006-DMN26D0UFB420V999MOHM10V3000MOHM45V4000MOHM25V014A0805A10V035W999NC10V0NC45VB; DRAWING: #NAME?; MAX_CURRENT: 0.805A; MAX_VOLTAGE: 20V; MAX_WATTAGE: 0.35W; NV_NAME: DMN26D0UFB4; NV_PN: 300-0868-000; PACK_TYPE: DFN1006; PATH: I3; PHYS_PAGE: 23; Q_G: 999nC@10V / 0nC@4.5V / 999nC@2.5V; ROT: 0; R_DS_ON: 999mohm@10V / 3000mohm@4.5V / 4000mohm@2.5V; SEC: 1; VER: 2; V_BE_GS: 10V; XY: (-8650,4850)
Q21 = Q_FET_N_ENH#1: ASSEMBLY: AUTOMATION; CDS_LIB: discrete; CDS_PART_NAME: Q_FET_N_ENH_DFN1006-DMN26D0UFB4,20V,999MOHM@10V / 3000MOHM@4.5V / 4000MOHM@2.5V,0.14A,0.805A,10V,0.35W,999NC@10V / 0NC@4.5V / A; CDS_PHYS_PART_NAME: Q_FET_N_ENH_DFN1006-DMN26D0UFB4,20V,999MOHM@10V / 3000MOHM@4.5V / 4000MOHM@2.5V,0.14A,0.805A,10V,0.35W,999NC@10V / 0NC@4.5V / B; CDS_SEC: 1; CONTINUOUS_CURRENT: 0.14A; CaptureCellPackProp: Q_FET_N_ENH##1; DEVICE_TYPENAME: Q_FET_N_ENH_DFN1006-DMN26D0UFB420V999MOHM10V3000MOHM45V4000MOHM25V014A0805A10V035W999NC10V0NC45VB; DRAWING: #NAME?; MAX_CURRENT: 0.805A; MAX_VOLTAGE: 20V; MAX_WATTAGE: 0.35W; NV_NAME: DMN26D0UFB4; NV_PN: 300-0868-000; PACK_TYPE: DFN1006; PATH: I21; PHYS_PAGE: 23; Q_G: 999nC@10V / 0nC@4.5V / 999nC@2.5V; ROT: 0; R_DS_ON: 999mohm@10V / 3000mohm@4.5V / 4000mohm@2.5V; SEC: 1; VER: 2; V_BE_GS: 10V; XY: (-1250,2200)
R119 = R: ASSEMBLY: FAN; CDS_LIB: discrete; CDS_PART_NAME: R_0402-100K,1 %,62.5MW,195-0005-000; CDS_PHYS_PART_NAME: R_0402-100K,1 %,62.5MW,195-0005-000-100K,195-0005-000; CDS_SEC: 1; DEVICE_TYPENAME: R_0402-100K1625MW195-0005-000-100K195-0005-000; DRAWING: #NAME?; MAX_WATTAGE: 62.5mW; NV_PN: 195-0005-000; PATH: I71; PHYS_PAGE: 23; ROT: 0; SEC: 1; SIGNAL_MODEL: nv_res; TOL: 1%; VER: 2; XY: (-10750,5500)
R120 = R#1: ASSEMBLY: DEBUG; CDS_LIB: discrete; CDS_PART_NAME: R_0402-0OHM,0.05 OHM,62.5MW,195-2655-000; CDS_PHYS_PART_NAME: R_0402-0OHM,0.05 OHM,62.5MW,195-2655-000-0OHM,195-2655-000; CDS_SEC: 1; CHIPS_PART_NAME: R; DEVICE_TYPENAME: R_0402-0OHM005OHM625MW195-2655-000-0OHM195-2655-000; DRAWING: #NAME?; MAX_WATTAGE: 62.5mW; NV_PN: 195-2655-000; PATH: I82; PHYS_PAGE: 23; ROT: 0; SEC: 1; SIGNAL_MODEL: nv_res; TOL: 0.05 ohm; VER: 1; XY: (-10600,2200)
R121 = R#1: ASSEMBLY: DEBUG; CDS_LIB: discrete; CDS_PART_NAME: R_0402-100K,1 %,62.5MW,195-0005-000; CDS_PHYS_PART_NAME: R_0402-100K,1 %,62.5MW,195-0005-000-100K,195-0005-000; CDS_SEC: 1; CHIPS_PART_NAME: R; DEVICE_TYPENAME: R_0402-100K1625MW195-0005-000-100K195-0005-000; DRAWING: #NAME?; MAX_WATTAGE: 62.5mW; NV_PN: 195-0005-000; PATH: I84; PHYS_PAGE: 23; ROT: 0; SEC: 1; SIGNAL_MODEL: nv_res; TOL: 1%; VER: 1; XY: (-10600,2050)
R122 = R: ASSEMBLY: FAN; CDS_LIB: discrete; CDS_PART_NAME: R_0402-4.7K,5 %,62.5MW,195-0598-000; CDS_PHYS_PART_NAME: R_0402-4.7K,5 %,62.5MW,195-0598-000-195-0598-000,4.7K; CDS_SEC: 1; DEVICE_TYPENAME: R_0402-47K5625MW195-0598-000-195-0598-00047K; DRAWING: #NAME?; MAX_WATTAGE: 62.5mW; NV_PN: 195-0598-000; PATH: I64; PHYS_PAGE: 23; ROT: 0; SEC: 1; SIGNAL_MODEL: nv_res; TOL: 5%; VER: 2; XY: (-9250,5500)
R123 = R: ASSEMBLY: FAN; CDS_LIB: discrete; CDS_PART_NAME: R_0402-10K,5 %,62.5MW,195-0486-000; CDS_PHYS_PART_NAME: R_0402-10K,5 %,62.5MW,195-0486-000-10K,195-0486-000; CDS_SEC: 1; DEVICE_TYPENAME: R_0402-10K5625MW195-0486-000-10K195-0486-000; DRAWING: #NAME?; MAX_WATTAGE: 62.5mW; NV_PN: 195-0486-000; PATH: I62; PHYS_PAGE: 23; ROT: 0; SEC: 1; SIGNAL_MODEL: nv_res; TOL: 5%; VER: 2; XY: (-9150,4650)
R124 = R: ASSEMBLY: FAN; CDS_LIB: discrete; CDS_PART_NAME: R_0402-10K,5 %,62.5MW,195-0486-000; CDS_PHYS_PART_NAME: R_0402-10K,5 %,62.5MW,195-0486-000-10K,195-0486-000; CDS_SEC: 1; DEVICE_TYPENAME: R_0402-10K5625MW195-0486-000-10K195-0486-000; DRAWING: #NAME?; MAX_WATTAGE: 62.5mW; NV_PN: 195-0486-000; PATH: I60; PHYS_PAGE: 23; ROT: 0; SEC: 1; SIGNAL_MODEL: nv_res; TOL: 5%; VER: 2; XY: (-8350,6050)
R125 = R: ASSEMBLY: DEBUG; CDS_LIB: discrete; CDS_PART_NAME: R_0402-100K,1 %,62.5MW,195-0005-000; CDS_PHYS_PART_NAME: R_0402-100K,1 %,62.5MW,195-0005-000-100K,195-0005-000; CDS_SEC: 1; DEVICE_TYPENAME: R_0402-100K1625MW195-0005-000-100K195-0005-000; DRAWING: #NAME?; MAX_WATTAGE: 62.5mW; NV_PN: 195-0005-000; PATH: I58; PHYS_PAGE: 23; ROT: 0; SEC: 1; SIGNAL_MODEL: nv_res; TOL: 1%; VER: 2; XY: (-8150,2650)
R126 = R: ASSEMBLY: L4T_EEPROM; CDS_LIB: discrete; CDS_PART_NAME: R_0402-10K,5 %,62.5MW,195-0486-000; CDS_PHYS_PART_NAME: R_0402-10K,5 %,62.5MW,195-0486-000-10K,195-0486-000; CDS_SEC: 1; DEVICE_TYPENAME: R_0402-10K5625MW195-0486-000-10K195-0486-000; DRAWING: #NAME?; MAX_WATTAGE: 62.5mW; NV_PN: 195-0486-000; PATH: I42; PHYS_PAGE: 23; ROT: 2; SEC: 1; SIGNAL_MODEL: nv_res; TOL: 5%; VER: 2; XY: (-4400,5650)
R127 = R: ASSEMBLY: L4T_EEPROM; CDS_LIB: discrete; CDS_PART_NAME: R_0402-10K,5 %,62.5MW,195-0486-000; CDS_PHYS_PART_NAME: R_0402-10K,5 %,62.5MW,195-0486-000-10K,195-0486-000; CDS_SEC: 1; DEVICE_TYPENAME: R_0402-10K5625MW195-0486-000-10K195-0486-000; DRAWING: #NAME?; MAX_WATTAGE: 62.5mW; NV_PN: 195-0486-000; PATH: I39; PHYS_PAGE: 23; ROT: 2; SEC: 1; SIGNAL_MODEL: nv_res; TOL: 5%; VER: 2; XY: (-4100,6250)
R128 = R: ASSEMBLY: L4T_EEPROM; CDS_LIB: discrete; CDS_PART_NAME: R_0402-10K,5 %,62.5MW,195-0486-000; CDS_PHYS_PART_NAME: R_0402-10K,5 %,62.5MW,195-0486-000-10K,195-0486-000; CDS_SEC: 1; DEVICE_TYPENAME: R_0402-10K5625MW195-0486-000-10K195-0486-000; DRAWING: #NAME?; MAX_WATTAGE: 62.5mW; NV_PN: 195-0486-000; PATH: I40; PHYS_PAGE: 23; ROT: 2; SEC: 1; SIGNAL_MODEL: nv_res; SKU: NO STUFF; TOL: 5%; VER: 2; XY: (-4100,5600)
R129 = R: ASSEMBLY: L4T_EEPROM; CDS_LIB: discrete; CDS_PART_NAME: R_0402-10K,5 %,62.5MW,195-0486-000; CDS_PHYS_PART_NAME: R_0402-10K,5 %,62.5MW,195-0486-000-10K,195-0486-000; CDS_SEC: 1; DEVICE_TYPENAME: R_0402-10K5625MW195-0486-000-10K195-0486-000; DRAWING: #NAME?; MAX_WATTAGE: 62.5mW; NV_PN: 195-0486-000; PATH: I17; PHYS_PAGE: 23; ROT: 2; SEC: 1; SIGNAL_MODEL: nv_res; TOL: 5%; VER: 2; XY: (-3800,6250)
R130 = R: ASSEMBLY: L4T_EEPROM; CDS_LIB: discrete; CDS_PART_NAME: R_0402-10K,5 %,62.5MW,195-0486-000; CDS_PHYS_PART_NAME: R_0402-10K,5 %,62.5MW,195-0486-000-10K,195-0486-000; CDS_SEC: 1; DEVICE_TYPENAME: R_0402-10K5625MW195-0486-000-10K195-0486-000; DRAWING: #NAME?; MAX_WATTAGE: 62.5mW; NV_PN: 195-0486-000; PATH: I18; PHYS_PAGE: 23; ROT: 2; SEC: 1; SIGNAL_MODEL: nv_res; SKU: NO STUFF; TOL: 5%; VER: 2; XY: (-3800,5600)
R131 = R: ASSEMBLY: L4T_EEPROM; CDS_LIB: discrete; CDS_PART_NAME: R_0402-10K,5 %,62.5MW,195-0486-000; CDS_PHYS_PART_NAME: R_0402-10K,5 %,62.5MW,195-0486-000-10K,195-0486-000; CDS_SEC: 1; DEVICE_TYPENAME: R_0402-10K5625MW195-0486-000-10K195-0486-000; DRAWING: #NAME?; MAX_WATTAGE: 62.5mW; NV_PN: 195-0486-000; PATH: I13; PHYS_PAGE: 23; ROT: 2; SEC: 1; SIGNAL_MODEL: nv_res; TOL: 5%; VER: 2; XY: (-3450,6250)
R132 = R: ASSEMBLY: L4T_EEPROM; CDS_LIB: discrete; CDS_PART_NAME: R_0402-10K,5 %,62.5MW,195-0486-000; CDS_PHYS_PART_NAME: R_0402-10K,5 %,62.5MW,195-0486-000-10K,195-0486-000; CDS_SEC: 1; DEVICE_TYPENAME: R_0402-10K5625MW195-0486-000-10K195-0486-000; DRAWING: #NAME?; MAX_WATTAGE: 62.5mW; NV_PN: 195-0486-000; PATH: I15; PHYS_PAGE: 23; ROT: 2; SEC: 1; SIGNAL_MODEL: nv_res; SKU: NO STUFF; TOL: 5%; VER: 2; XY: (-3450,5600)
R133 = R#1: ASSEMBLY: AUTOMATION; CDS_LIB: discrete; CDS_PART_NAME: R_0402-0OHM,0.05 OHM,62.5MW,195-2655-000; CDS_PHYS_PART_NAME: R_0402-0OHM,0.05 OHM,62.5MW,195-2655-000-0OHM,195-2655-000; CDS_SEC: 1; CHIPS_PART_NAME: R; DEVICE_TYPENAME: R_0402-0OHM005OHM625MW195-2655-000-0OHM195-2655-000; DRAWING: #NAME?; MAX_WATTAGE: 62.5mW; NV_PN: 195-2655-000; PATH: I26; PHYS_PAGE: 23; ROT: 0; SEC: 1; SIGNAL_MODEL: nv_res; TOL: 0.05 ohm; VER: 1; XY: (-2100,2300)
R134 = R#1: ASSEMBLY: AUTOMATION; CDS_LIB: discrete; CDS_PART_NAME: R_0402-0OHM,0.05 OHM,62.5MW,195-2655-000; CDS_PHYS_PART_NAME: R_0402-0OHM,0.05 OHM,62.5MW,195-2655-000-0OHM,195-2655-000; CDS_SEC: 1; CHIPS_PART_NAME: R; DEVICE_TYPENAME: R_0402-0OHM005OHM625MW195-2655-000-0OHM195-2655-000; DRAWING: #NAME?; MAX_WATTAGE: 62.5mW; NV_PN: 195-2655-000; PATH: I27; PHYS_PAGE: 23; ROT: 0; SEC: 1; SIGNAL_MODEL: nv_res; SKU: NO STUFF; TOL: 0.05 ohm; VER: 1; XY: (-2100,2150)
R135 = R: ASSEMBLY: AUTOMATION; CDS_LIB: discrete; CDS_PART_NAME: R_0402-10K,5 %,62.5MW,195-0486-000; CDS_PHYS_PART_NAME: R_0402-10K,5 %,62.5MW,195-0486-000-10K,195-0486-000; CDS_SEC: 1; DEVICE_TYPENAME: R_0402-10K5625MW195-0486-000-10K195-0486-000; DRAWING: #NAME?; MAX_WATTAGE: 62.5mW; NV_PN: 195-0486-000; PATH: I23; PHYS_PAGE: 23; ROT: 0; SEC: 1; SIGNAL_MODEL: nv_res; TOL: 5%; VER: 2; XY: (-1600,2550)
R136 = R: ASSEMBLY: AUTOMATION; CDS_LIB: discrete; CDS_PART_NAME: R_0402-499OHM,1 %,62.5MW,195-0338-000; CDS_PHYS_PART_NAME: R_0402-499OHM,1 %,62.5MW,195-0338-000-195-0338-000,499OHM; CDS_SEC: 1; DEVICE_TYPENAME: R_0402-499OHM1625MW195-0338-000-195-0338-000499OHM; DRAWING: #NAME?; MAX_WATTAGE: 62.5mW; NV_PN: 195-0338-000; PATH: I20; PHYS_PAGE: 23; ROT: 0; SEC: 1; SIGNAL_MODEL: nv_res; TOL: 1%; VER: 2; XY: (-1150,2800)
R223 = R: ASSEMBLY: AUTOMATION; CDS_LIB: discrete; CDS_PART_NAME: R_0402-10K,5 %,62.5MW,195-0486-000; CDS_PHYS_PART_NAME: R_0402-10K,5 %,62.5MW,195-0486-000-10K,195-0486-000; CDS_SEC: 1; DEVICE_TYPENAME: R_0402-10K5625MW195-0486-000-10K195-0486-000; DRAWING: #NAME?; MAX_WATTAGE: 62.5mW; NV_PN: 195-0486-000; PATH: I97; PHYS_PAGE: 23; ROT: 0; SEC: 1; SIGNAL_MODEL: nv_res; TOL: 5%; VER: 2; XY: (-3000,2800)
U15 = U_LEVSHFT_3STATE#1: ASSEMBLY: FAN; CDS_LIB: logic; CDS_PART_NAME: U_LEVSHFT_3STATE_SC70_6-SN74LVC1T45DCKR,LEVEL SHIFTER,115-2544-000; CDS_PHYS_PART_NAME: U_LEVSHFT_3STATE_SC70_6-SN74LVC1T45DCKR,LEVEL SHIFTER,115-2544-000-115-2544-000; CDS_SEC: 1; DEVICE_TYPENAME: U_LEVSHFT_3STATE_SC70_6-SN74LVC1T45DCKRLEVELSHIFTER115-2544-000-115-2544-000; DRAWING: #NAME?; FUNCTION: Level Shifter; NV_NAME: SN74LVC1T45DCKR; NV_PN: 115-2544-000; PATH: I96; PHYS_PAGE: 23; ROT: 2; SEC: 1; VER: 1; XY: (-9950,5650)
U16 = U_LEVSHFT_TXB0302: ASSEMBLY: DEBUG; CDS_LIB: logic; CDS_PART_NAME: U_LEVSHFT_TXB0302_DFN8-TXB0302DQMR,LEVEL SHIFTER,115-2177-000; CDS_PHYS_PART_NAME: U_LEVSHFT_TXB0302_DFN8-TXB0302DQMR,LEVEL SHIFTER,115-2177-000-115-2177-000; CDS_SEC: 1; DEVICE_TYPENAME: U_LEVSHFT_TXB0302_DFN8-TXB0302DQMRLEVELSHIFTER115-2177-000-115-2177-000; DRAWING: #NAME?; FUNCTION: Level Shifter; NV_NAME: TXB0302DQMR; NV_PN: 115-2177-000; PATH: I75; PHYS_PAGE: 23; ROT: 0; SEC: 1; VER: 1; XY: (-8800,2350)
U17 = U_MEM_EE_I2C: ASSEMBLY: L4T_EEPROM; CDS_LIB: memory; CDS_PART_NAME: U_MEM_EE_I2C_DFN08-1MHZ,1.7V..3.6V,AT24C02D-MAHM-T,174-0159-000; CDS_PHYS_PART_NAME: U_MEM_EE_I2C_DFN08-1MHZ,1.7V..3.6V,AT24C02D-MAHM-T,174-0159-000-174-0159-000; CDS_SEC: 1; DEVICE_TYPENAME: U_MEM_EE_I2C_DFN08-1MHZ17V36VAT24C02D-MAHM-T174-0159-000-174-0159-000; DRAWING: #NAME?; NV_NAME: AT24C02D-MAHM-T; NV_PN: 174-0159-000; PACK_TYPE: DFN08; PATH: I14; PHYS_PAGE: 23; POW: 1.7V..3.6V; ROT: 0; SEC: 1; SPEED_GRADE: 1MHz; VER: 2; XY: (-3000,5800)
VS16 = VIRTUAL_SHORT#1: ASSEMBLY: AUTOMATION; CDS_LIB: mechanic; CDS_PART_NAME: VIRTUAL_SHORT_SHUNT-VIRTUAL_SHORT; CDS_PHYS_PART_NAME: VIRTUAL_SHORT_SHUNT-VIRTUAL_SHORT; CDS_SEC: 1; DEVICE_TYPENAME: VIRTUAL_SHORT_SHUNT-VIRTUAL_SHORT; DRAWING: #NAME?; PACK_TYPE: SHUNT; PATH: I51; PHYS_PAGE: 23; ROT: 0; SEC: 1; VER: 2; XY: (-5500,3600)
VS19 = VIRTUAL_SHORT#1: ASSEMBLY: AUTOMATION; CDS_LIB: mechanic; CDS_PART_NAME: VIRTUAL_SHORT_SHUNT-VIRTUAL_SHORT; CDS_PHYS_PART_NAME: VIRTUAL_SHORT_SHUNT-VIRTUAL_SHORT; CDS_SEC: 1; DEVICE_TYPENAME: VIRTUAL_SHORT_SHUNT-VIRTUAL_SHORT; DRAWING: #NAME?; PACK_TYPE: SHUNT; PATH: I92; PHYS_PAGE: 23; ROT: 0; SEC: 1; VER: 2; XY: (-8650,6750)
MEC3 = MOUNTING_HOLE: ASSEMBLY: NONPHYSICAL; CDS_LIB: mechanic; CDS_PART_NAME: MOUNTING_HOLE_X2-P3509_MOUNTING_HOLE; CDS_PHYS_PART_NAME: MOUNTING_HOLE_X2-P3509_MOUNTING_HOLE; CDS_SEC: 2; DEVICE_TYPENAME: MOUNTING_HOLE_X2-P3509_MOUNTING_HOLE; DRAWING: #NAME?; NV_NAME: P3509_MOUNTING_HOLE; PACK_TYPE: X2; PATH: I2; PHYS_PAGE: 24; ROT: 0; SEC: 2; SEC_TYPE: X2; VER: 1; XY: (-5850,4400)

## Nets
GND: C124.2 C125.2 C126.2 C128.2 C129.1 C130.2 C132.2 C133.2 C134.2 D42.2 D43.2 D44.2 D45.2 D46.2 D48.2 D49.2 J12.6 J12.9 J12.14 J12.20 J12.25 J12.30 J12.34 J12.39 J13.1 J14.7 J14.9 J14.11 MEC3.1(GND) MEC3.2(GND) Q21.2(S) R116.1 R119.2 R121.1 R122.2 R126.2 R128.2 R130.2 R132.2 R179.2 R180.2 R223.2 U12.11(GND) U12.21(EP) U13.11(GND) U13.21(EP) U14.11(GND) U14.21(EP) U15.2(GND) U15.5(DIR) U16.4(GND) U17.4(GND) U17.9(TP) ; also on sheet 4 5 6 7 8 9 10 11 12 13 14 15 16 17 18 19 21
VDD_1V8: C124.1 C129.2 C134.1 Q20.1(G) R115.1 R120.1 R123.1 R127.1 R129.1 R131.1 R135.1 U12.2(VCCA) U13.2(VCCA) U14.2(VCCA) U15.6(VCCB) U16.1(VCCA) U17.8(VCC) ; also on sheet 4 5 8 9 15 19 21
VDD_3V3_SYS: C125.1 C126.1 C130.1 J12.1 J12.17 R117.1 R118.1 R125.1 U12.19(VCCB) U13.19(VCCB) U14.19(VCCB) U16.8(VCCB) ; also on sheet 4 5 6 7 8 9 12 15 16 19 20 21
VDD_5V_GPIO: C128.1 J12.2 J12.4 Q23.2(S) Q24.4(E)
VDD_5V_SYS: Q23.3(D) Q24.1(E) U15.1(VCCA) VS16.1(A) VS19.1(A) ; also on sheet 8 9 10 11 12 14 15 16 17 21
AUTO_ON_DIS: J14.6 R223.1
BD_DISABLE: Q24.2(B) Q24.5(B) Q24.6(C) R179.1
BMCU_ACOK: D46.1 J14.5 ; also on sheet 14
BOARD_ID_A0: R131.2 R132.1 U17.1(A0)
BOARD_ID_WP: R126.1 U17.7(WP)
BRD_ID_A1: R129.2 R130.1 U17.2(A1)
BRD_ID_A2: R127.2 R128.1 U17.3(A2)
EN_PWR_PATH: Q23.1(G) Q24.3(C) R180.1
FAN_PWM: R119.1 U15.4(B) ; also on sheet 20
FAN_PWM_Q*: J13.4 R122.1 U15.3(A)
FAN_TACH: Q20.2(S) R123.2 ; also on sheet 20
FAN_TACH_CON: J13.3 Q20.3(D) R124.2
FAN_VDD: C132.1 J13.2 R124.1 VS19.2(B)
FORCE_RECOVERY*: J14.10 ; also on sheet 21
GPIO01: U13.9(A8) ; also on sheet 20
GPIO01_LS: J12.29 U13.12(B8)
GPIO07: U12.7(A6) ; also on sheet 20
GPIO07_LS: J12.32 U12.14(B6)
GPIO09: U13.6(A5) ; also on sheet 20
GPIO09_LS: J12.7 U13.15(B5)
GPIO11: U13.8(A7) ; also on sheet 20
GPIO11_LS: J12.31 U13.13(B7)
GPIO12: U12.8(A7) ; also on sheet 20
GPIO12_LS: J12.15 U12.13(B7)
GPIO13: U13.7(A6) ; also on sheet 20
GPIO13_LS: J12.33 U13.14(B6)
I2C1_SCL: D44.1 J12.5 ; also on sheet 21
I2C1_SDA: D45.1 J12.3 ; also on sheet 21
I2C2_SCL: U17.6(SCL) ; also on sheet 4 5 21
I2C2_SDA: U17.5(SDA) ; also on sheet 4 5 21
I2S0_LRCK: U13.5(A4) ; also on sheet 20
I2S0_LRCK_LS: J12.35 U13.16(B4)
I2S0_SCLK: U13.1(A1) ; also on sheet 20
I2S0_SCLK_LS: J12.12 U13.20(B1)
I2S0_SDIN: U13.4(A3) ; also on sheet 20
I2S0_SDIN_LS: J12.38 U13.17(B3)
I2S0_SDOUT: U13.3(A2) ; also on sheet 20
I2S0_SDOUT_LS: J12.40 U13.18(B2)
ID_I2C_SCL: D42.1 J12.28 ; also on sheet 21
ID_I2C_SDA: D43.1 J12.27 ; also on sheet 21
LED1_CTRL: Q21.1(G) R133.2 R134.2 R135.2
LS_ENABLE: R115.2 R116.2 U12.10(OE) U13.10(OE) U14.10(OE)
MOD_SLEEP*: R134.1 ; also on sheet 9 21
PC_LED+: J14.2 VS16.2(B)
PC_LED-: J14.1 R136.1
PC_LED_R: Q21.3(D) R136.2
PWR_BTN*: J14.12 ; also on sheet 14 21
PWR_LED_CTRL: R133.1 ; also on sheet 20 21
SPI0_CS0: U12.5(A4) ; also on sheet 20
SPI0_CS0_LS: J12.24 U12.16(B4)
SPI0_CS1: U12.6(A5) ; also on sheet 20
SPI0_CS1_LS: J12.26 U12.15(B5)
SPI0_MISO: U12.3(A2) ; also on sheet 20
SPI0_MISO_LS: J12.21 U12.18(B2)
SPI0_MOSI: U12.4(A3) ; also on sheet 20
SPI0_MOSI_LS: J12.19 U12.17(B3)
SPI0_SCK: U12.1(A1) ; also on sheet 20
SPI0_SCK_LS: J12.23 U12.20(B1)
SPI1_CS0: U14.5(A4) ; also on sheet 20
SPI1_CS0_LS: J12.18 U14.16(B4)
SPI1_CS1: U14.6(A5) ; also on sheet 20
SPI1_CS1_LS: J12.16 U14.15(B5)
SPI1_MISO: U14.3(A2) ; also on sheet 20
SPI1_MISO_LS: J12.22 U14.18(B2)
SPI1_MOSI: U14.4(A3) ; also on sheet 20
SPI1_MOSI_LS: J12.37 U14.17(B3)
SPI1_SCK: U14.1(A1) ; also on sheet 20
SPI1_SCK_LS: J12.13 U14.20(B1)
SYS_RST*: C133.1 J14.8 ; also on sheet 14 21
UART1_CTS: U14.9(A8) ; also on sheet 21
UART1_CTS_LS: J12.36 R118.2 U14.12(B8)
UART1_RTS: U12.9(A8) ; also on sheet 21
UART1_RTS_LS: J12.11 U12.12(B8)
UART1_RXD: U14.8(A7) ; also on sheet 21
UART1_RXD_LS: J12.10 R117.2 U14.13(B7)
UART1_TXD: U14.7(A6) ; also on sheet 21
UART1_TXD_LS: J12.8 U14.14(B6)
UART2_LS_OE: R120.2 R121.2 U16.5(OE)
UART2_RXD: U16.2(A1) ; also on sheet 21
UART2_RXD_LS: D48.1 J14.3 R125.2 U16.7(B1)
UART2_TXD: U16.3(A2) ; also on sheet 21
UART2_TXD_LS: D49.1 J14.4 U16.6(B2)

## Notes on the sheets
sheet 1
- A
- B
- C
- D
- E
- F
- G
- H
- MECHANICAL
- 1
- 1
- 2
- Mounting holes for Module
- 2
- 3
- 3
- 4
- 4
- 5
- 5
- NVIDIA CORPORATION
- 2701 SAN TOMAS EXPRESSWAY
- ASSEMBLY
- <ASSEMBLY_DESCRIPTION>
- SANTA CLARA, CA 95050, USA
- PAGE DETAIL
- MECHANICAL
- NV_PN
- 600-13509-BASE-100
- ALL NVIDIA DESIGN SPECIFICATIONS, REFERENCE SPECIFICATIONS, REFERENCE BOARDS, FILES, DRAWINGS, DIAGNOSTICS, LISTS AND OTHER DOCUMENTS OR INFORMATION (TOGETHER AND SEPARATELY, 'MATERIALS') ARE BEING PROVIDED 'AS IS'. THE MATERIALS MAY
- CONTAIN KNOWN AND UNKNOWN VIOLATIONS OR DEVIATIONS OF INDUSTRY STANDARDS AND SPECIFICATIONS. NVIDIA MAKES NO WARRANTIES, EXPRESSED, IMPLIED, STATUTORY OR OTHERWISE WITH RESPECT TO THE MATERIALS OR OTHERWISE, AND EXPRESSLY DISCLAIMS ALL
- PCB REV
- P3509-A01
- PAGE
- 24 OF 25
- IMPLIED WARRANTIES INCLUDING, WITHOUT LIMITATION, THE WARRANTIES OF DESIGN, OF NONINFRINGEMENT, MERCHANTABILITY OR FITNESS FOR A PARTICULAR PURPOSE, OR ARISING FROM A COURSE OF DEALING, TRADE USAGE, TRADE PRACTICE, OR INDUSTRY STANDARDS.
- BOM REV
- <BOM_REV>
- DATE
- 27-NOV-2019
- A
- B
- C
- D
- E
- F
- G
- H
sheet 2
- A
- B
- C
- D
- E
- F
- G
- H
- SoC Fan Header 4pin
- Carrier board config
- 1
- 1
- GND
- PWR
- PWM
- TACH
- 7'b1010xxx
- 7'b1010111 = 7'h57
- 2
- 2
- Vgs(th) = 0.45 to 1.05V
- Button Header Pinout
- Serial Port
- 3
- 3
- 4
- 4
- 5
- 5
- NVIDIA CORPORATION
- 2701 SAN TOMAS EXPRESSWAY
- ASSEMBLY
- <ASSEMBLY_DESCRIPTION>
- SANTA CLARA, CA 95050, USA
- PAGE DETAIL
- FAN, DEBUG and EEPROM
- NV_PN
- 600-13509-BASE-100
- ALL NVIDIA DESIGN SPECIFICATIONS, REFERENCE SPECIFICATIONS, REFERENCE BOARDS, FILES, DRAWINGS, DIAGNOSTICS, LISTS AND OTHER DOCUMENTS OR INFORMATION (TOGETHER AND SEPARATELY, 'MATERIALS') ARE BEING PROVIDED 'AS IS'. THE MATERIALS MAY
- CONTAIN KNOWN AND UNKNOWN VIOLATIONS OR DEVIATIONS OF INDUSTRY STANDARDS AND SPECIFICATIONS. NVIDIA MAKES NO WARRANTIES, EXPRESSED, IMPLIED, STATUTORY OR OTHERWISE WITH RESPECT TO THE MATERIALS OR OTHERWISE, AND EXPRESSLY DISCLAIMS ALL
- PCB REV
- P3509-A01
- PAGE
- 23 OF 25
- IMPLIED WARRANTIES INCLUDING, WITHOUT LIMITATION, THE WARRANTIES OF DESIGN, OF NONINFRINGEMENT, MERCHANTABILITY OR FITNESS FOR A PARTICULAR PURPOSE, OR ARISING FROM A COURSE OF DEALING, TRADE USAGE, TRADE PRACTICE, OR INDUSTRY STANDARDS.
- BOM REV
- <BOM_REV>
- DATE
- 27-NOV-2019
- A
- B
- C
- D
- E
- F
- G
- H
sheet 3
- A
- B
- C
- D
- E
- F
- G
- H
- 40PIN GPIO EXPANSION HDR
- 1
- 1
- Place close to U22, U48, U7
- 2
- 2
- IDEAL DIODE REVERSE CURRENT BLOCK
- BACK POWER ALLOWED FROM 40PIN
- 3
- 3
- 40pin HDR
- 4
- 4
- 5
- 5
- NVIDIA CORPORATION
- 2701 SAN TOMAS EXPRESSWAY
- ASSEMBLY
- <ASSEMBLY_DESCRIPTION>
- SANTA CLARA, CA 95050, USA
- PAGE DETAIL
- 40PIN GPIO Expansion HDR
- NV_PN
- 600-13509-BASE-100
- ALL NVIDIA DESIGN SPECIFICATIONS, REFERENCE SPECIFICATIONS, REFERENCE BOARDS, FILES, DRAWINGS, DIAGNOSTICS, LISTS AND OTHER DOCUMENTS OR INFORMATION (TOGETHER AND SEPARATELY, 'MATERIALS') ARE BEING PROVIDED 'AS IS'. THE MATERIALS MAY
- CONTAIN KNOWN AND UNKNOWN VIOLATIONS OR DEVIATIONS OF INDUSTRY STANDARDS AND SPECIFICATIONS. NVIDIA MAKES NO WARRANTIES, EXPRESSED, IMPLIED, STATUTORY OR OTHERWISE WITH RESPECT TO THE MATERIALS OR OTHERWISE, AND EXPRESSLY DISCLAIMS ALL
- PCB REV
- P3509-A01
- PAGE
- 22 OF 25
- IMPLIED WARRANTIES INCLUDING, WITHOUT LIMITATION, THE WARRANTIES OF DESIGN, OF NONINFRINGEMENT, MERCHANTABILITY OR FITNESS FOR A PARTICULAR PURPOSE, OR ARISING FROM A COURSE OF DEALING, TRADE USAGE, TRADE PRACTICE, OR INDUSTRY STANDARDS.
- BOM REV
- <BOM_REV>
- DATE
- 27-NOV-2019
- A
- B
- C
- D
- E
- F
- G
- H
